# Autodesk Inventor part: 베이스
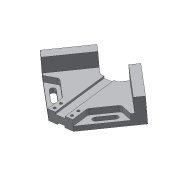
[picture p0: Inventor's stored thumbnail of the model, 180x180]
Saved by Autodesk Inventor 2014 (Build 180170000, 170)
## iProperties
Created: 2019-04
Part Number: 베이스
Material: 알루미늄 6061
Document SubType Name: Modeling
Designer: 601-25
Density: 2.71 g/cm^3
Appearance: 알루미늄 - 평지
Mass: 606.494 g
Surface Area: 425.254 cm^2
Volume: 223.799 cm^3
Author: 601-25
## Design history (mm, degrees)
sketch "스케치1"
  geometry: L1 (0, 0)-(0, 93); L2 (0, 93)-(14.088, 93); L3 (14.088, 93)-(35.322, 114.193); L4 (35.322, 114.193)-(84.772, 64.648); L5 (84.772, 64.648)-(20, 0); L6 (20, 0)-(0, 0); L7 (24.705, 103.596)-(74.155, 54.052); L8 (0, 93)-(0, 149.582); L9 (35.322, 114.193)-(0, 149.582); L10 (20, 0)-(20, 28.257); L11 (20, 28.257)-(49.41, 57.611); L12 (49.41, 57.611)-(70.616, 50.52); L13 (0, 93)-(-14.088, 93); L14 (-14.088, 93)-(-35.322, 114.193); L15 (-35.322, 114.193)-(-84.772, 64.648); L16 (-84.772, 64.648)-(-20, 0); L17 (-20, 0)-(0, 0); L18 (-24.705, 103.596)-(-74.155, 54.052); L19 (-35.322, 114.193)-(0, 149.582); L20 (-20, 0)-(-20, 28.257); L21 (-20, 28.257)-(-49.41, 57.611); L22 (-49.41, 57.611)-(-70.616, 50.52); L23 (-49.41, 57.611)-(-63.538, 43.455); L24 (-20, 28.257)-(-34.129, 14.102); L25 (-50.623, 51.051)-(-26.558, 27.032); L26 (-26.558, 27.032)-(-32.916, 20.662); L27 (-32.916, 20.662)-(-56.98, 44.681); L28 (-56.98, 44.681)-(-50.623, 51.051); L29 (-34.705, 42.934)-(-38.59, 39.041); L30 (-53.801, 47.866)-(-56.474, 50.533); L31 (53.801, 47.866)-(56.474, 50.533); L32 (56.98, 44.681)-(50.623, 51.051); L33 (34.705, 42.934)-(38.59, 39.041); L34 (50.623, 51.051)-(26.558, 27.032); L35 (26.558, 27.032)-(32.916, 20.662); L36 (32.916, 20.662)-(56.98, 44.681)
  constraints: 72 end point, 17 symmetric about line, 9 parallel, 8 perpendicular, 6 point on line, 5 midpoint, 1 vertical
  dimensions: "d0" = 93 distance between parallel lines of L2 L6; "d1" = 40 diameter of L5.end L1; "d2" = 50 distance of L8.end L3.end; "d3" = 120 distance of L8.end L4.end; "d4" = 15 distance between parallel lines of L4 L7; "d5" = 20 distance of L12.end L4.end; "d6" = 20 distance from line of L5 L11.end; "d16" = 30 distance of L23.end L15.end; "d17" = 34 distance of L26.end L27.end; "d18" = 9 distance of L27.end L25.start
extrude "돌출2" new body sketch "스케치1" distance "d10" = 42; taper "d11" = 0 deg
extrude "돌출3" join sketch "스케치1" distance "d12" = 18; taper "d13" = 0 deg
extrude "돌출4" join sketch "스케치1" distance "d14" = 8; taper "d15" = 0 deg
extrude "돌출5" cut sketch "스케치1" stored distance "d19" = 8; taper "d20" = 0 deg
fillet "모깎기1" dims "d21" = 5
fillet "모깎기2" dims "d22" = 5
sketch "스케치3"
  geometry: L1 (-20, 0)-(20, 0) reference; L2 (14.088, 93)-(-14.088, 93) reference; L3 (-8, 93)-(8, 93); L4 (8, 93)-(8, 0); L5 (8, 0)-(-8, 0); L6 (-8, 0)-(-8, 93); L7 (-20, 28.257)-(-20, 0) reference; L8 (-14, 0)-(-14, 36.662); L9 (0, 0)-(0, 93) reference; 9 further points
  constraints: 10 end point, 6 midpoint, 5 point on line, 3 parallel, 2 symmetric about line, 1 coincident, 1 horizontal, 1 perpendicular
  dimensions: "d23" = 16 distance of L3.start L3.end; "d29" = 28 diameter of point (-14, 6) L9; "d30" = 6 distance from line of point (-14, 6) L1; "d31" = 12 distance of point (-14, 18) point (-14, 6)
extrude "돌출6" cut sketch "스케치3" distance "d24" = 3.5; taper "d25" = 0 deg
sketch "스케치4"
  geometry: L1 (20, 0)-(-20, 0) reference; L2 (-14.088, 93)-(14.088, 93) reference; L3 (-6, 93)-(6, 93); L4 (6, 93)-(6, 0); L5 (6, 0)-(-6, 0); L6 (-6, 0)-(-6, 93); 7 further points
  constraints: 8 end point, 2 midpoint, 2 parallel, 2 point on line, 1 coincident, 1 horizontal, 1 perpendicular
  dimensions: "d26" = 12 distance of L4.end L5.end
extrude "돌출7" cut sketch "스케치4" distance "d27" = 3; taper "d28" = 0 deg
hole "구멍1" sketch "스케치3" diameter "d32" = 4.5; stored, may be unused: countersink angle "d36" = 90 deg, drill point angle "d38" = 0 deg; dims "d33" = 6, "d34" = 4, "d35" = 2, "d37" = 8
hole "구멍2" sketch "스케치3" diameter "d39" = 4.5; stored, may be unused: countersink angle "d43" = 90 deg, drill point angle "d45" = 0 deg; dims "d40" = 6, "d41" = 4, "d42" = 2, "d44" = 8
hole "구멍3" sketch "스케치4" diameter "d46" = 8; stored, may be unused: countersink angle "d50" = 90 deg, drill point angle "d52" = 0 deg; dims "d47" = 6, "d48" = 4, "d49" = 2, "d51" = 10
fillet "모깎기3" dims "d53" = 5
sketch "스케치5"
  geometry: L1 (-35.322, 114.193)-(-84.772, 64.648) reference; L2 (-84.772, 64.648)-(-74.155, 54.052) reference; L3 (-74.155, 54.052)-(-24.705, 103.596) reference; L4 (-24.705, 103.596)-(-35.322, 114.193) reference; 1 further point
sketch "스케치6"
  geometry: L1 (-35.322, 114.193)-(-84.772, 64.648) reference; L2 (-84.772, 64.648)-(-74.155, 54.052) reference; L3 (-74.155, 54.052)-(-24.705, 103.596) reference; L4 (-24.705, 103.596)-(-35.322, 114.193) reference; 1 further point
node "솔리드2"
